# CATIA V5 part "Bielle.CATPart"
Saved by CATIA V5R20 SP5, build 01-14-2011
Part number: Bielle
Bounding box of the stored display mesh (mm): x -80 to 80, y -79.951 to 79.951, z -40 to 20
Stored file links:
  F:\IAO_bmadec\bmadecf\Bielle.CATPart
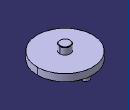
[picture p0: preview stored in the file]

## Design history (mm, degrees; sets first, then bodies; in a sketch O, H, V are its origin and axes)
Body1 (main body)
  Sketch1 on xy-plane, origin (0, 0, 0), H (1, 0, 0), V (0, 1, 0)
    circle A1 centre (0, 0) radius 15
    radius A1 = 15
  Pad1: profile Sketch1, direction (0, 0, 1), length 20
  Sketch2 on start face of Pad1, origin (0, 0, 0), H (1, 0, 0), V (0, -1, 0)
    circle A1 centre (0, 0) radius 80
    radius A1 = 80
  Pad2: profile Sketch2, direction (0, 0, -1), length 20
  Sketch3 on end face of Pad2, origin (0, 0, -20), H (1, 0, 0), V (0, -1, 0)
    circle A1 centre (0, -60) radius 10
    point P1 (0, -60)
    radius A1 = 10
    distance P1 H = 60
    coincidence: P1 V
  Pad3: profile Sketch3, direction (0, 0, -1), length 20
  Chamfer1: length 1, angle 45, on edge [face of Pad3 from Sketch3.A1 | end face of Pad3]
  Chamfer2: length 1, angle 45, on end face of Pad1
